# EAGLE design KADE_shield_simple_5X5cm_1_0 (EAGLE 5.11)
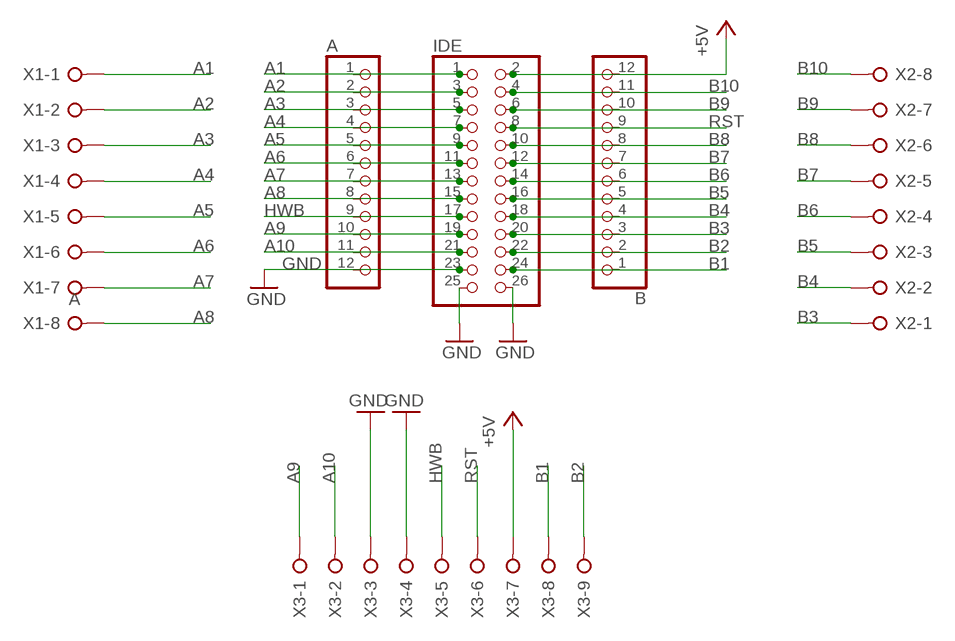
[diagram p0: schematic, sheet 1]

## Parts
A  PINHD-1X12  [1X12]
B  PINHD-1X12  [1X12]
IDE  PINHD-2X13  [2X13]
X1  A  W237-08P  [W237-8P]
X2  W237-08P  [W237-8P]
X3  W237-09P  [W237-9P]

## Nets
+5V: B.12 IDE.2 X3.7
A1: A.1 IDE.1 X1.1
A2: A.2 IDE.3 X1.2
A3: A.3 IDE.5 X1.3
A4: A.4 IDE.7 X1.4
A5: A.5 IDE.9 X1.5
A6: A.6 IDE.11 X1.6
A7: A.7 IDE.13 X1.7
A8: A.8 IDE.15 X1.8
A9: A.10 IDE.19 X3.1
A10: A.11 IDE.21 X3.2
B1: B.1 IDE.24 X3.8
B2: B.2 IDE.22 X3.9
B3: B.3 IDE.20 X2.1
B4: B.4 IDE.18 X2.2
B5: B.5 IDE.16 X2.3
B6: B.6 IDE.14 X2.4
B7: B.7 IDE.12 X2.5
B8: B.8 IDE.10 X2.6
B9: B.10 IDE.6 X2.7
B10: B.11 IDE.4 X2.8
GND: A.12 IDE.23 IDE.25 IDE.26 X3.3 X3.4
HWB: A.9 IDE.17 X3.5
RST: B.9 IDE.8 X3.6

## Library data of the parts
A B = pinhead:PINHD-1X12: PIN HEADER
IDE = pinhead:PINHD-2X13: PIN HEADER
X1 X2 = con-wago-508:W237-08P: WAGO SREW CLAMP; OC_FARNELL: unknown; OC_NEWARK: unknown
X3 = con-wago-508:W237-09P: WAGO SREW CLAMP; OC_FARNELL: unknown; OC_NEWARK: unknown

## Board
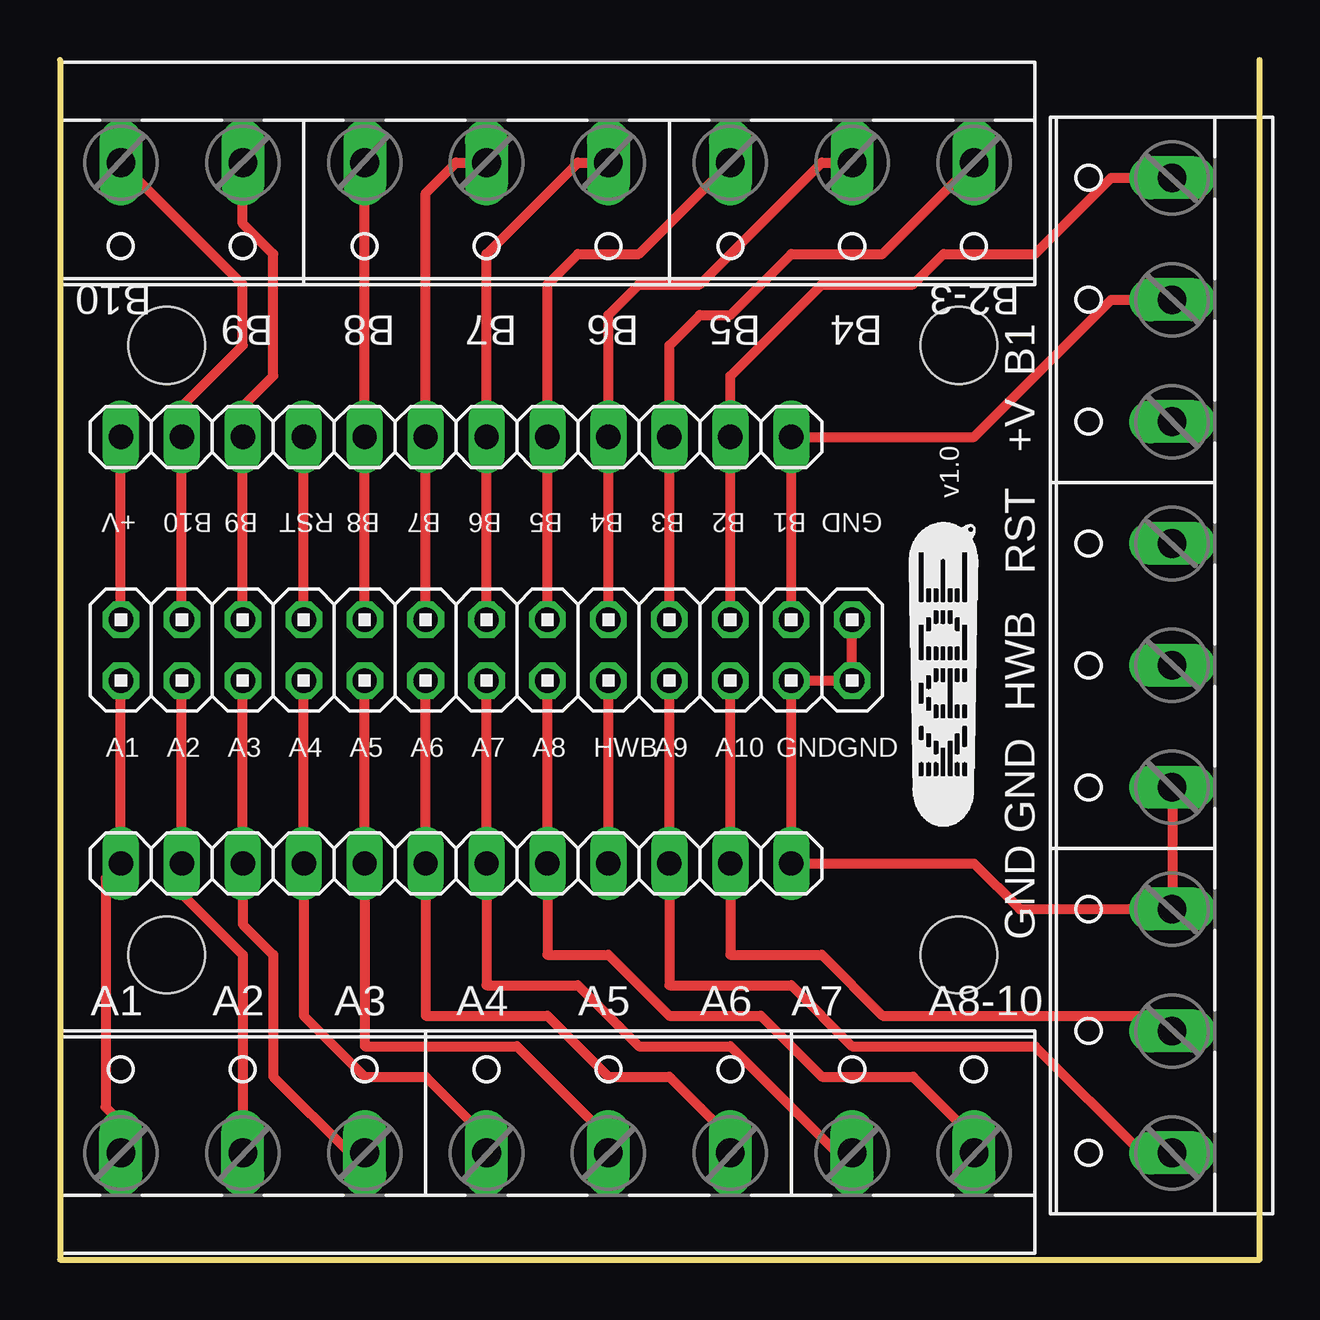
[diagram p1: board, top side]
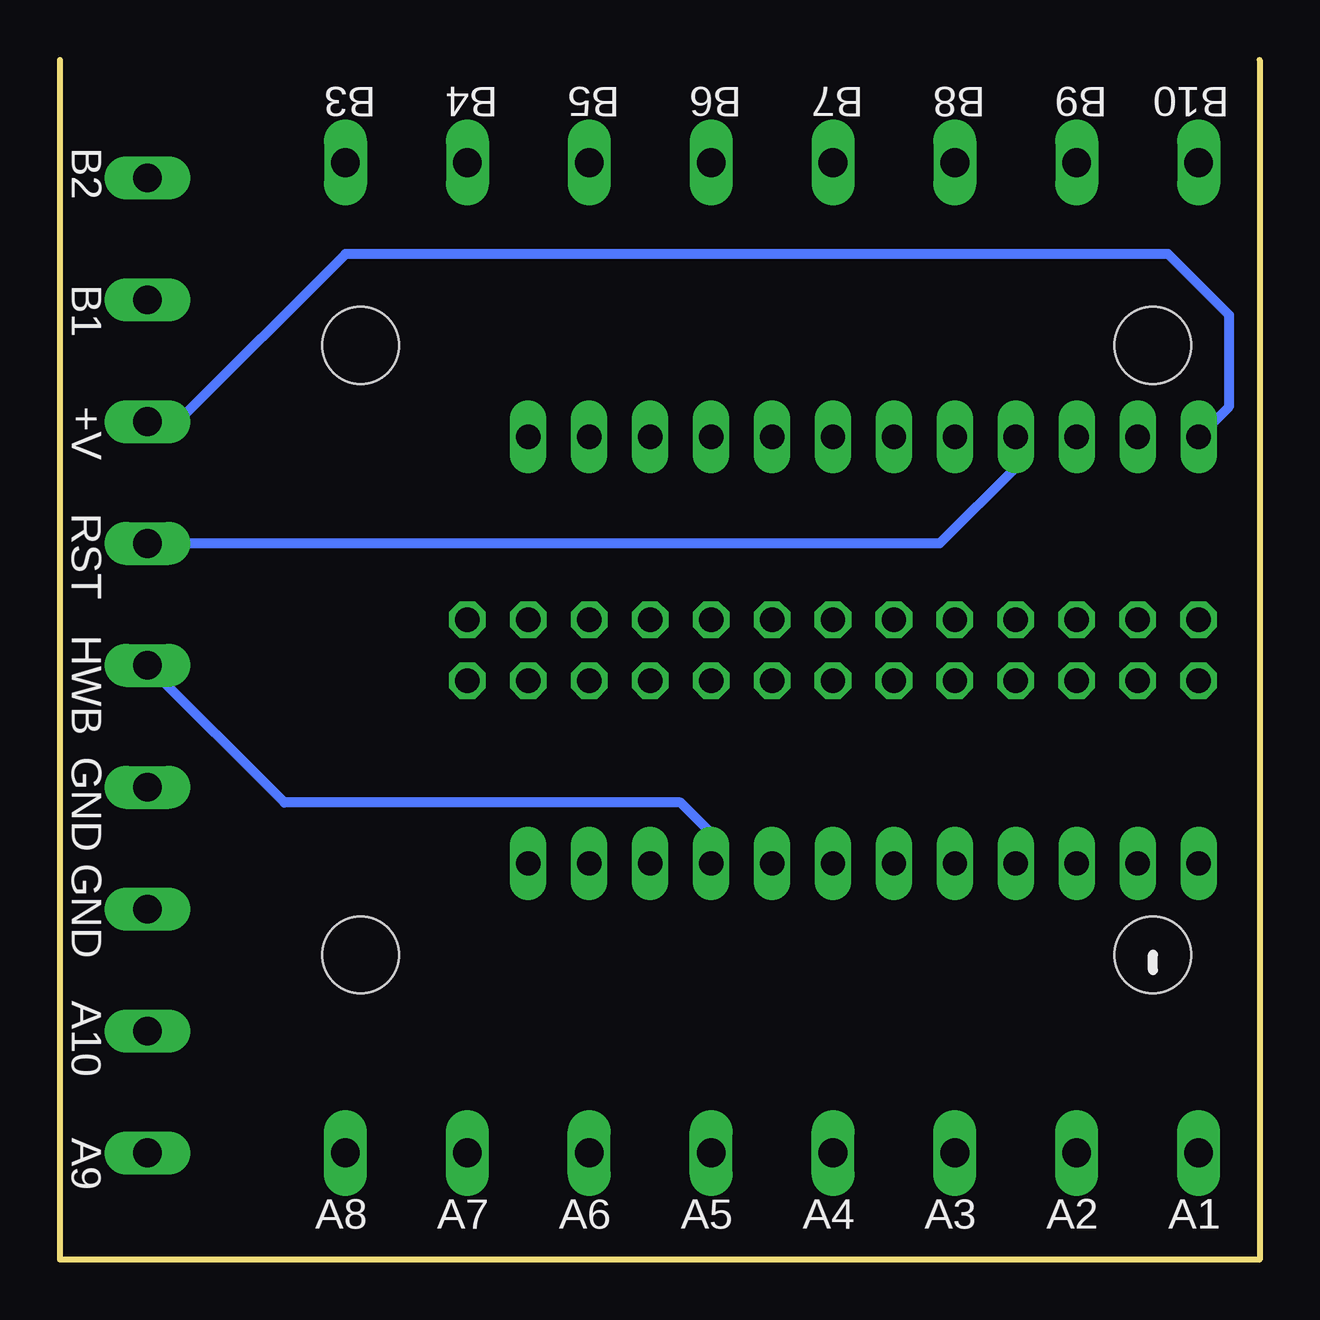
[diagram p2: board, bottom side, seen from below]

Size 50 x 50 mm. Coordinates in mm from the lower left corner, seen from the top.
Outline: 50,50 50,0 0,0 0,50
Copper layers (1*16): Top 0.035mm / dielectric 1.5mm / Bottom 0.035mm
Design rules "default": minimum track width 10mil, minimum drill 24mil, track to track 8mil, track to pad 8mil, pad to pad 8mil, via to via 8mil, smd to smd 8mil, copper to edge 40mil, drill to drill 8mil, minimum pad ring 10mil, minimum via ring 8mil, stop-mask expansion 4mil, vias tented up to drill 0mil, thermal gap 10mil
Holes 3.2 mm at 37.47,38.1 37.47,12.7 4.45,12.7 4.45,38.1

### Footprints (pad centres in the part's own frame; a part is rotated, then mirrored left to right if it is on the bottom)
1X12 = drill 1.016 long: 1 -13.97,0; 2 -11.43,0; 3 -8.89,0; 4 -6.35,0; 5 -3.81,0; 6 -1.27,0; 7 1.27,0; 8 3.81,0; 9 6.35,0; 10 8.89,0; 11 11.43,0; 12 13.97,0
2X13 = drill 1.016 octagon: 1 -15.24,-1.27; 2 -15.24,1.27; 3 -12.7,-1.27; 4 -12.7,1.27; 5 -10.16,-1.27; 6 -10.16,1.27; 7 -7.62,-1.27; 8 -7.62,1.27; 9 -5.08,-1.27; 10 -5.08,1.27; 11 -2.54,-1.27; 12 -2.54,1.27; 13 0,-1.27; 14 0,1.27; 15 2.54,-1.27; 16 2.54,1.27; 17 5.08,-1.27; 18 5.08,1.27; 19 7.62,-1.27; 20 7.62,1.27; 21 10.16,-1.27; 22 10.16,1.27; 23 12.7,-1.27; 24 12.7,1.27; 25 15.24,-1.27; 26 15.24,1.27
W237-8P = drill 1.194 long: 1 -17.78,-0.635; 2 -12.7,-0.635; 3 -7.62,-0.635; 4 -2.54,-0.635; 5 2.54,-0.635; 6 7.62,-0.635; 7 12.7,-0.635; 8 17.78,-0.635
W237-9P = drill 1.194 long: 1 -20.32,-0.635; 2 -15.24,-0.635; 3 -10.16,-0.635; 4 -5.08,-0.635; 5 0,-0.635; 6 5.08,-0.635; 7 10.16,-0.635; 8 15.24,-0.635; 9 20.32,-0.635

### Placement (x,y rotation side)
A  16.51,16.51 0 top
B  16.51,34.29 180 top
IDE  17.78,25.4 0 top
X1  20.32,5.08 0 top
X2  20.32,45.09 180 top
X3  45.72,24.77 90 top

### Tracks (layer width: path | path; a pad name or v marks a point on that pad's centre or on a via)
+5V
  Top 0.406: IDE.2 B.12
  Bottom 0.406: B.12 1.27,35.56 1.27,39.37 3.81,41.91 38.1,41.91 45.09,34.92 X3.7
A1
  Top 0.406: IDE.1 A.1 1.91,15.88 1.91,6.35 2.54,5.71 X1.1
A2
  Top 0.406: IDE.3 A.2 5.08,15.24 7.62,12.7 X1.2
A3
  Top 0.406: IDE.5 A.3 7.62,13.97 8.89,12.7 8.89,7.62 12.06,4.45 X1.3
A4
  Top 0.406: IDE.7 A.4 10.16,10.16 12.7,7.62 15.24,7.62 17.78,5.08 X1.4
A5
  Top 0.406: IDE.9 A.5 12.7,8.89 19.05,8.89 22.86,5.08 X1.5
A6
  Top 0.406: IDE.11 A.6 15.24,10.16 20.32,10.16 22.86,7.62 25.4,7.62 27.94,5.08 X1.6
A7
  Top 0.406: IDE.13 A.7 17.78,11.43 21.59,11.43 24.13,8.89 27.94,8.89 32.38,4.45 X1.7
A8
  Top 0.406: IDE.15 A.8 20.32,12.7 22.86,12.7 25.4,10.16 29.21,10.16 31.75,7.62 35.56,7.62 38.1,5.08 X1.8
A9
  Top 0.406: IDE.19 A.10 25.4,11.43 30.48,11.43 33.02,8.89 40.64,8.89 45.09,4.45 X3.1
A10
  Top 0.406: IDE.21 A.11 27.94,12.7 31.75,12.7 34.29,10.16 45.72,10.16 X3.2
B1
  Top 0.406: IDE.24 B.1 38.1,34.29 43.81,40.01 X3.8
B2
  Top 0.406: IDE.22 B.2 27.94,36.83 31.75,40.64 35.56,40.64 36.83,41.91 40.64,41.91 43.81,45.09 X3.9
B3
  Top 0.406: IDE.20 B.3 25.4,38.1 26.67,39.37 27.94,39.37 30.48,41.91 34.29,41.91 X2.1
B4
  Top 0.406: IDE.18 B.4 22.86,39.37 24.13,40.64 26.67,40.64 31.75,45.72 X2.2
B5
  Top 0.406: IDE.16 B.5 20.32,40.64 21.59,41.91 24.13,41.91 X2.3
B6
  Top 0.406: IDE.14 B.6 17.78,41.91 21.59,45.72 X2.4
B7
  Top 0.406: IDE.12 B.7 15.24,44.45 16.51,45.72 X2.5
B8
  Top 0.406: IDE.10 B.8 X2.6
B9
  Top 0.406: IDE.6 B.10 7.62,35.56 8.89,36.83 8.89,41.91 7.62,43.18 X2.7
B10
  Top 0.406: IDE.4 B.11 5.08,35.56 7.62,38.1 7.62,40.64 X2.8
GND
  Top 0.406: IDE.26 IDE.25 IDE.23 A.12 38.1,16.51 40.01,14.61 X3.3 X3.4
HWB
  Top 0.406: A.9 IDE.17
  Bottom 0.406: X3.5 40.64,19.05 24.13,19.05 22.86,17.78 A.9
RST
  Top 0.406: IDE.8 B.9
  Bottom 0.406: B.9 10.16,33.02 13.34,29.84 X3.6

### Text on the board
tPlace: B10 | B2-3 | B9 | B8 | B7 | B6 | B5 | B4 | B1 | +V | v1.0 | +V | B10 | B9 | RST | B8 | B7 | B6 | B5 | B4 | B3 | B2 | B1 | GND | RST | HWB | A1 | A2 | A3 | A4 | A5 | A6 | A7 | A8 | HWB | A9 | A10 | GND | GND | GND | GND | A1 | A2 | A3 | A4 | A5 | A6 | A7 | A8-10
bPlace: B10 | B9 | B8 | B7 | B6 | B5 | B4 | B3 | B2 | B1 | +V | RST | HWB | GND | GND | A10 | A9 | A1 | A2 | A3 | A4 | A5 | A6 | A7 | A8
